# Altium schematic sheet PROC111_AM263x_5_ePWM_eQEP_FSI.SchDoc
size 431 x 279 mm; Date: Not shown in title block; ApprovedBy: Not shown in title block; CheckedBy: Not shown in title block; Author: Not shown in title block; CompanyName: Not shown in title block; Engineer: Not shown in title block; Organization: Not shown in title block; Address1: Not shown in title block; Address2: Not shown in title block; Address3: Not shown in title block; Address4: Not shown in title block; DocumentNumber: 9; Revision: Use project parameter SCH_Rev; SheetNumber: 9; SheetTotal: 24; PageSetup: Record=PageOptions¦CenterHorizontal=True¦CenterVertical=True¦PrintScale=1.00¦XCorrection=1.00¦YCorrection=1.00¦PrintKind=0¦BorderSize=5000000¦LeftOffset=0¦BottomOffset=0¦Orientation=2¦PaperLength=1000¦PaperWidth=1000¦Scale=100¦PaperSource=15¦PrintQuality=600¦MediaType=1¦DitherType=10¦PaperKind=Letter¦PrintScaleMode=1
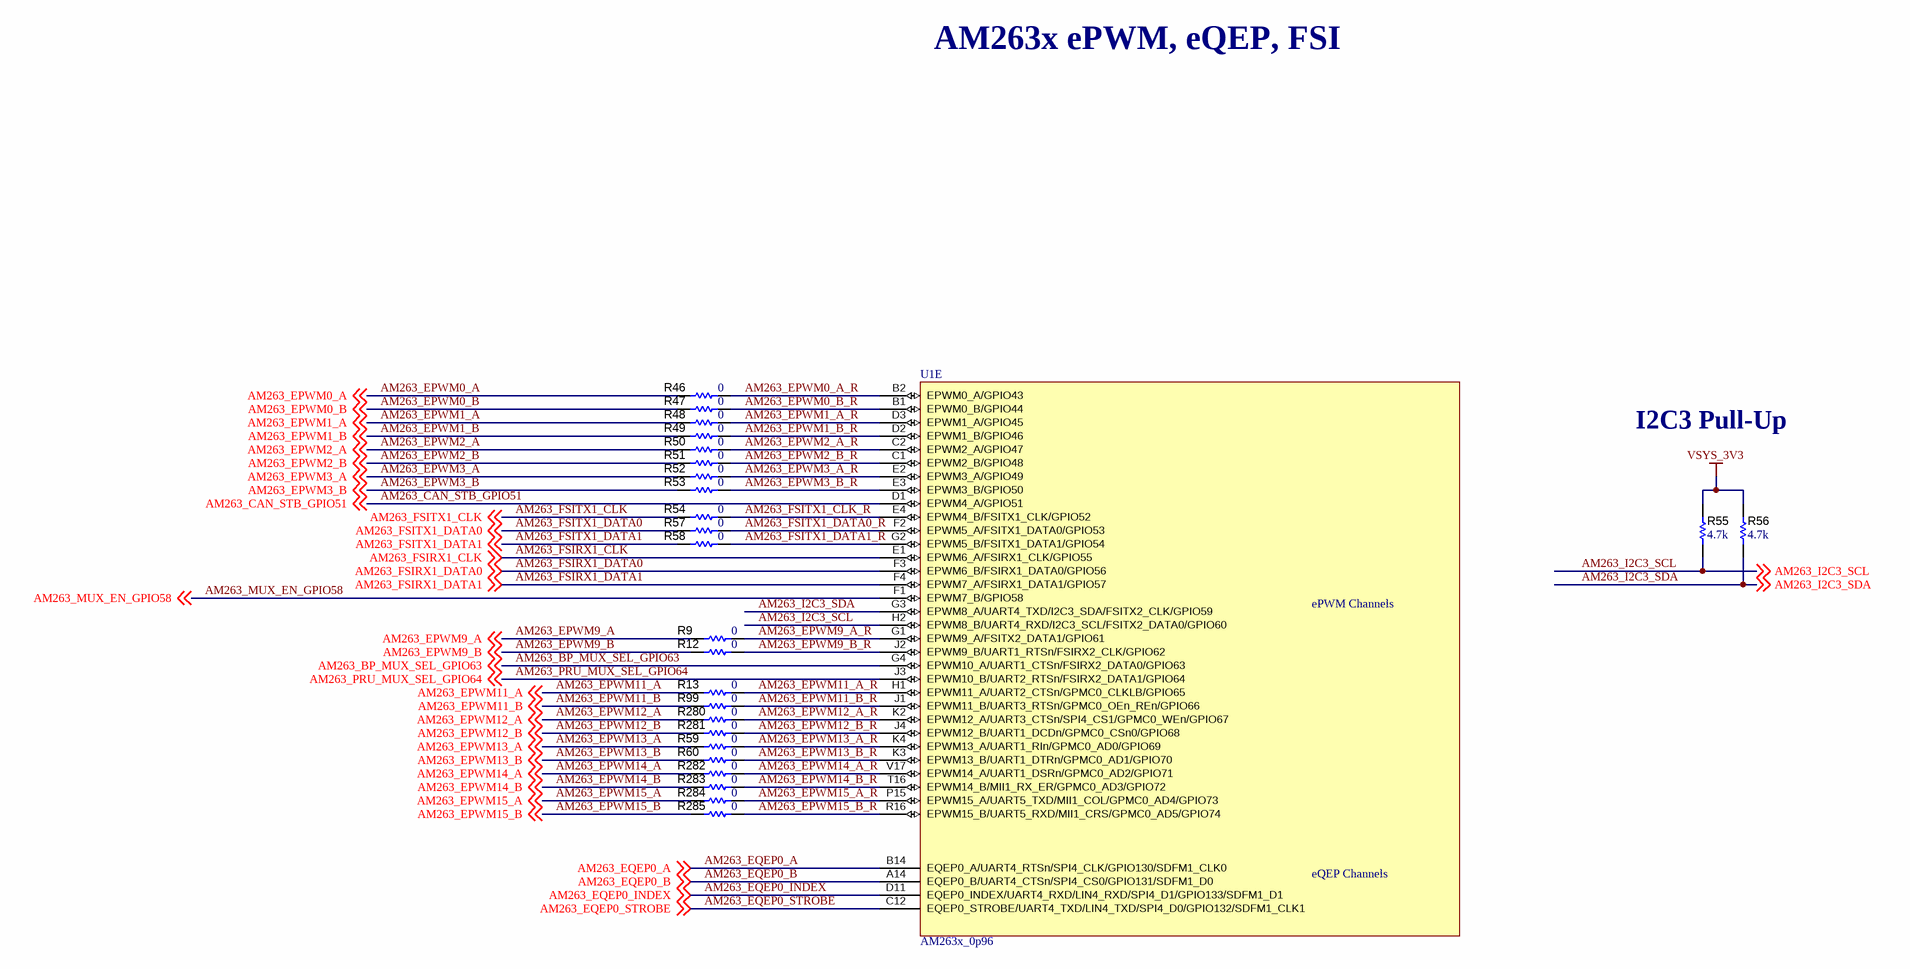
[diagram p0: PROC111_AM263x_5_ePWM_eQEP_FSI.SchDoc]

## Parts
R9  value 0  [0402L]  (hidden comment: ERJ-2GE0R00X)
R12  value 0  [0402L]  (hidden comment: ERJ-2GE0R00X)
R13  value 0  [0402L]  (hidden comment: ERJ-2GE0R00X)
R46  value 0  [0402L]  (hidden comment: ERJ-2GE0R00X)
R47  value 0  [0402L]  (hidden comment: ERJ-2GE0R00X)
R48  value 0  [0402L]  (hidden comment: ERJ-2GE0R00X)
R49  value 0  [0402L]  (hidden comment: ERJ-2GE0R00X)
R50  value 0  [0402L]  (hidden comment: ERJ-2GE0R00X)
R51  value 0  [0402L]  (hidden comment: ERJ-2GE0R00X)
R52  value 0  [0402L]  (hidden comment: ERJ-2GE0R00X)
R53  value 0  [0402L]  (hidden comment: ERJ-2GE0R00X)
R54  value 0  [0402L]  (hidden comment: ERJ-2GE0R00X)
R55  ValueDisplayed: 4.7k  [0402]  (hidden comment: CRCW04024K70JNED)
R56  ValueDisplayed: 4.7k  [0402]  (hidden comment: CRCW04024K70JNED)
R57  value 0  [0402L]  (hidden comment: ERJ-2GE0R00X)
R58  value 0  [0402L]  (hidden comment: ERJ-2GE0R00X)
R59  value 0  [0402L]  (hidden comment: ERJ-2GE0R00X)
R60  value 0  [0402L]  (hidden comment: ERJ-2GE0R00X)
R99  value 0  [0402L]  (hidden comment: ERJ-2GE0R00X)
R280  value 0  [0402L]  (hidden comment: ERJ-2GE0R00X)
R281  value 0  [0402L]  (hidden comment: ERJ-2GE0R00X)
R282  value 0  [0402L]  (hidden comment: ERJ-2GE0R00X)
R283  value 0  [0402L]  (hidden comment: ERJ-2GE0R00X)
R284  value 0  [0402L]  (hidden comment: ERJ-2GE0R00X)
R285  value 0  [0402L]  (hidden comment: ERJ-2GE0R00X)
U1  AM263x_0p96  [ZCZ (S-PBGA-N324)]  (part E of 13)

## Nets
VSYS_3V3: R55.2 R56.2
AM263_BP_MUX_SEL_GPIO63: U1.G4(EPWM10_A/UART1_CTSn/FSIRX2_DATA0/GPIO63) ; off-sheet AM263_BP_MUX_SEL_GPIO63
AM263_CAN_STB_GPIO51: U1.D1(EPWM4_A/GPIO51) ; off-sheet AM263_CAN_STB_GPIO51
AM263_EPWM0_A: R46.1 ; off-sheet AM263_EPWM0_A
AM263_EPWM0_A_R: R46.2 U1.B2(EPWM0_A/GPIO43)
AM263_EPWM0_B: R47.1 ; off-sheet AM263_EPWM0_B
AM263_EPWM0_B_R: R47.2 U1.B1(EPWM0_B/GPIO44)
AM263_EPWM1_A: R48.1 ; off-sheet AM263_EPWM1_A
AM263_EPWM1_A_R: R48.2 U1.D3(EPWM1_A/GPIO45)
AM263_EPWM1_B: R49.1 ; off-sheet AM263_EPWM1_B
AM263_EPWM1_B_R: R49.2 U1.D2(EPWM1_B/GPIO46)
AM263_EPWM2_A: R50.1 ; off-sheet AM263_EPWM2_A
AM263_EPWM2_A_R: R50.2 U1.C2(EPWM2_A/GPIO47)
AM263_EPWM2_B: R51.1 ; off-sheet AM263_EPWM2_B
AM263_EPWM2_B_R: R51.2 U1.C1(EPWM2_B/GPIO48)
AM263_EPWM3_A: R52.1 ; off-sheet AM263_EPWM3_A
AM263_EPWM3_A_R: R52.2 U1.E2(EPWM3_A/GPIO49)
AM263_EPWM3_B: R53.1 ; off-sheet AM263_EPWM3_B
AM263_EPWM3_B_R: R53.2 U1.E3(EPWM3_B/GPIO50)
AM263_EPWM9_A: R9.1 ; off-sheet AM263_EPWM9_A
AM263_EPWM9_A_R: R9.2 U1.G1(EPWM9_A/FSITX2_DATA1/GPIO61)
AM263_EPWM9_B: R12.1 ; off-sheet AM263_EPWM9_B
AM263_EPWM9_B_R: R12.2 U1.J2(EPWM9_B/UART1_RTSn/FSIRX2_CLK/GPIO62)
AM263_EPWM11_A: R13.1 ; off-sheet AM263_EPWM11_A
AM263_EPWM11_A_R: R13.2 U1.H1(EPWM11_A/UART2_CTSn/GPMC0_CLKLB/GPIO65)
AM263_EPWM11_B: R99.1 ; off-sheet AM263_EPWM11_B
AM263_EPWM11_B_R: R99.2 U1.J1(EPWM11_B/UART3_RTSn/GPMC0_OEn_REn/GPIO66)
AM263_EPWM12_A: R280.1 ; off-sheet AM263_EPWM12_A
AM263_EPWM12_A_R: R280.2 U1.K2(EPWM12_A/UART3_CTSn/SPI4_CS1/GPMC0_WEn/GPIO67)
AM263_EPWM12_B: R281.1 ; off-sheet AM263_EPWM12_B
AM263_EPWM12_B_R: R281.2 U1.J4(EPWM12_B/UART1_DCDn/GPMC0_CSn0/GPIO68)
AM263_EPWM13_A: R59.1 ; off-sheet AM263_EPWM13_A
AM263_EPWM13_A_R: R59.2 U1.K4(EPWM13_A/UART1_RIn/GPMC0_AD0/GPIO69)
AM263_EPWM13_B: R60.1 ; off-sheet AM263_EPWM13_B
AM263_EPWM13_B_R: R60.2 U1.K3(EPWM13_B/UART1_DTRn/GPMC0_AD1/GPIO70)
AM263_EPWM14_A: R282.1 ; off-sheet AM263_EPWM14_A
AM263_EPWM14_A_R: R282.2 U1.V17(EPWM14_A/UART1_DSRn/GPMC0_AD2/GPIO71)
AM263_EPWM14_B: R283.1 ; off-sheet AM263_EPWM14_B
AM263_EPWM14_B_R: R283.2 U1.T16(EPWM14_B/MII1_RX_ER/GPMC0_AD3/GPIO72)
AM263_EPWM15_A: R284.1 ; off-sheet AM263_EPWM15_A
AM263_EPWM15_A_R: R284.2 U1.P15(EPWM15_A/UART5_TXD/MII1_COL/GPMC0_AD4/GPIO73)
AM263_EPWM15_B: R285.1 ; off-sheet AM263_EPWM15_B
AM263_EPWM15_B_R: R285.2 U1.R16(EPWM15_B/UART5_RXD/MII1_CRS/GPMC0_AD5/GPIO74)
AM263_EQEP0_A: U1.B14(EQEP0_A/UART4_RTSn/SPI4_CLK/GPIO130/SDFM1_CLK0) ; off-sheet AM263_EQEP0_A
AM263_EQEP0_B: U1.A14(EQEP0_B/UART4_CTSn/SPI4_CS0/GPIO131/SDFM1_D0) ; off-sheet AM263_EQEP0_B
AM263_EQEP0_INDEX: U1.D11(EQEP0_INDEX/UART4_RXD/LIN4_RXD/SPI4_D1/GPIO133/SDFM1_D1) ; off-sheet AM263_EQEP0_INDEX
AM263_EQEP0_STROBE: U1.C12(EQEP0_STROBE/UART4_TXD/LIN4_TXD/SPI4_D0/GPIO132/SDFM1_CLK1) ; off-sheet AM263_EQEP0_STROBE
AM263_FSIRX1_CLK: U1.E1(EPWM6_A/FSIRX1_CLK/GPIO55) ; off-sheet AM263_FSIRX1_CLK
AM263_FSIRX1_DATA0: U1.F3(EPWM6_B/FSIRX1_DATA0/GPIO56) ; off-sheet AM263_FSIRX1_DATA0
AM263_FSIRX1_DATA1: U1.F4(EPWM7_A/FSIRX1_DATA1/GPIO57) ; off-sheet AM263_FSIRX1_DATA1
AM263_FSITX1_CLK: R54.1 ; off-sheet AM263_FSITX1_CLK
AM263_FSITX1_CLK_R: R54.2 U1.E4(EPWM4_B/FSITX1_CLK/GPIO52)
AM263_FSITX1_DATA0: R57.1 ; off-sheet AM263_FSITX1_DATA0
AM263_FSITX1_DATA0_R: R57.2 U1.F2(EPWM5_A/FSITX1_DATA0/GPIO53)
AM263_FSITX1_DATA1: R58.1 ; off-sheet AM263_FSITX1_DATA1
AM263_FSITX1_DATA1_R: R58.2 U1.G2(EPWM5_B/FSITX1_DATA1/GPIO54)
AM263_I2C3_SCL: R55.1 U1.H2(EPWM8_B/UART4_RXD/I2C3_SCL/FSITX2_DATA0/GPIO60) ; off-sheet AM263_I2C3_SCL
AM263_I2C3_SDA: R56.1 U1.G3(EPWM8_A/UART4_TXD/I2C3_SDA/FSITX2_CLK/GPIO59) ; off-sheet AM263_I2C3_SDA
AM263_MUX_EN_GPIO58: U1.F1(EPWM7_B/GPIO58) ; off-sheet AM263_MUX_EN_GPIO58
AM263_PRU_MUX_SEL_GPIO64: U1.J3(EPWM10_B/UART2_RTSn/FSIRX2_DATA1/GPIO64) ; off-sheet AM263_PRU_MUX_SEL_GPIO64

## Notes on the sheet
- AM263x ePWM, eQEP, FSI
- I2C3 Pull-Up

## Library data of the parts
R9 R12 R13 R46-R54 R57-R60 R99 R280-R285 = CMP-0026992-3: RES, 0, 5%, 0.1 W, AEC-Q200 Grade 0, 0402; Manufacturer: Panasonic; Power_W: 100mW; TempCo: 600 ppm/C; Value_Code: 0000; EIA_Code: E24; SizeX_mm: 1; SizeY_mm: 0.5; SizeZ_mm: 0.6; Value2: 0.1W; AEC Qualified: Y; VDC_V: 50V; AEC Category: Q200; SizeAreaWB_mm2: 3
R55 R56 = CMP-0026938-5: RES, 4.7 k, 5%, 0.063 W, AEC-Q200 Grade 0, 0402; Manufacturer: Vishay-Dale; Power_W: 63mW; TempCo: 200 ppm/C; Value_Code: 4k70; Value: 4.7k; EIA_Code: E24; SizeX_mm: 1; SizeY_mm: 0.5; SizeZ_mm: 0.6; Value2: 0.063W; AEC Qualified: Y; VDC_V: 50V; AEC Category: Q200; AEC Grade: 0
U1 = AM263x_0p96: Sitara AM263x MCU (Pinlist Revision 0.96, Pinmux 0.98)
